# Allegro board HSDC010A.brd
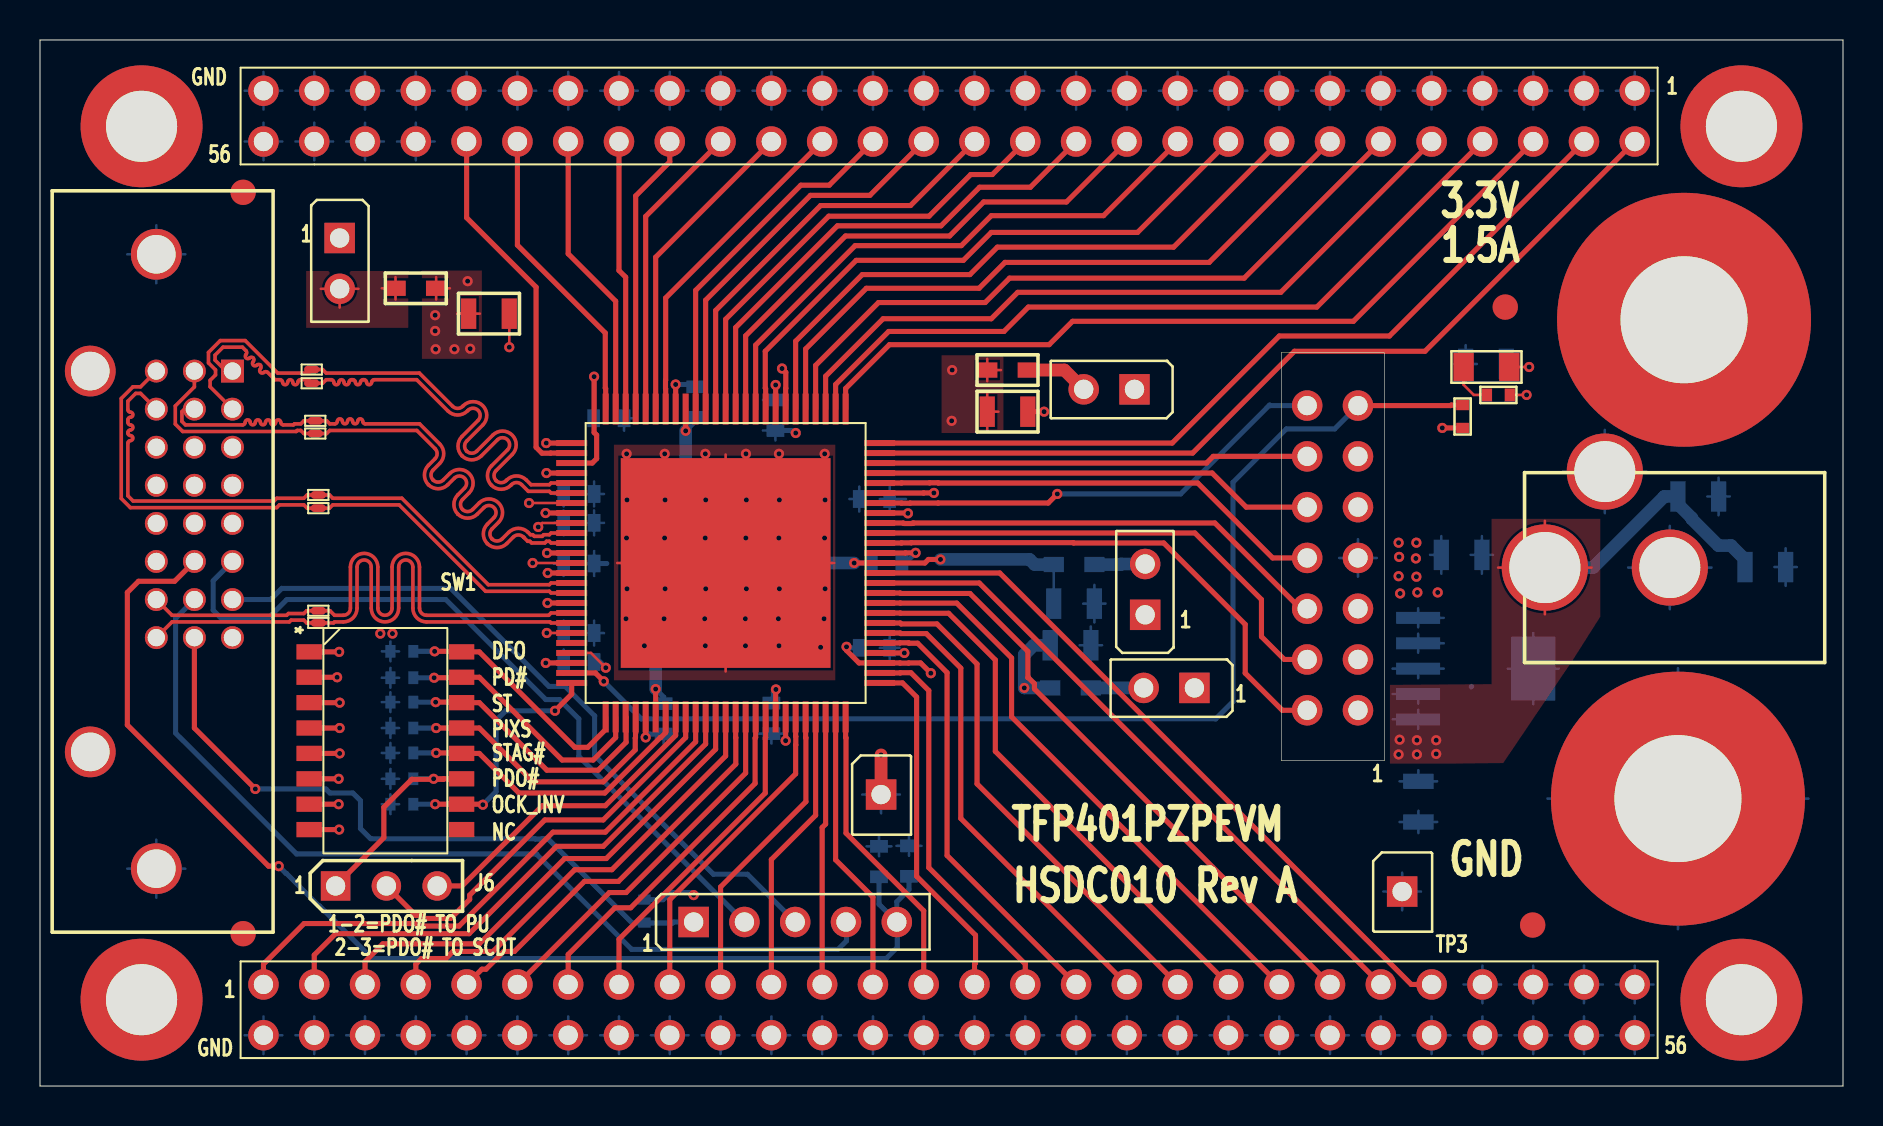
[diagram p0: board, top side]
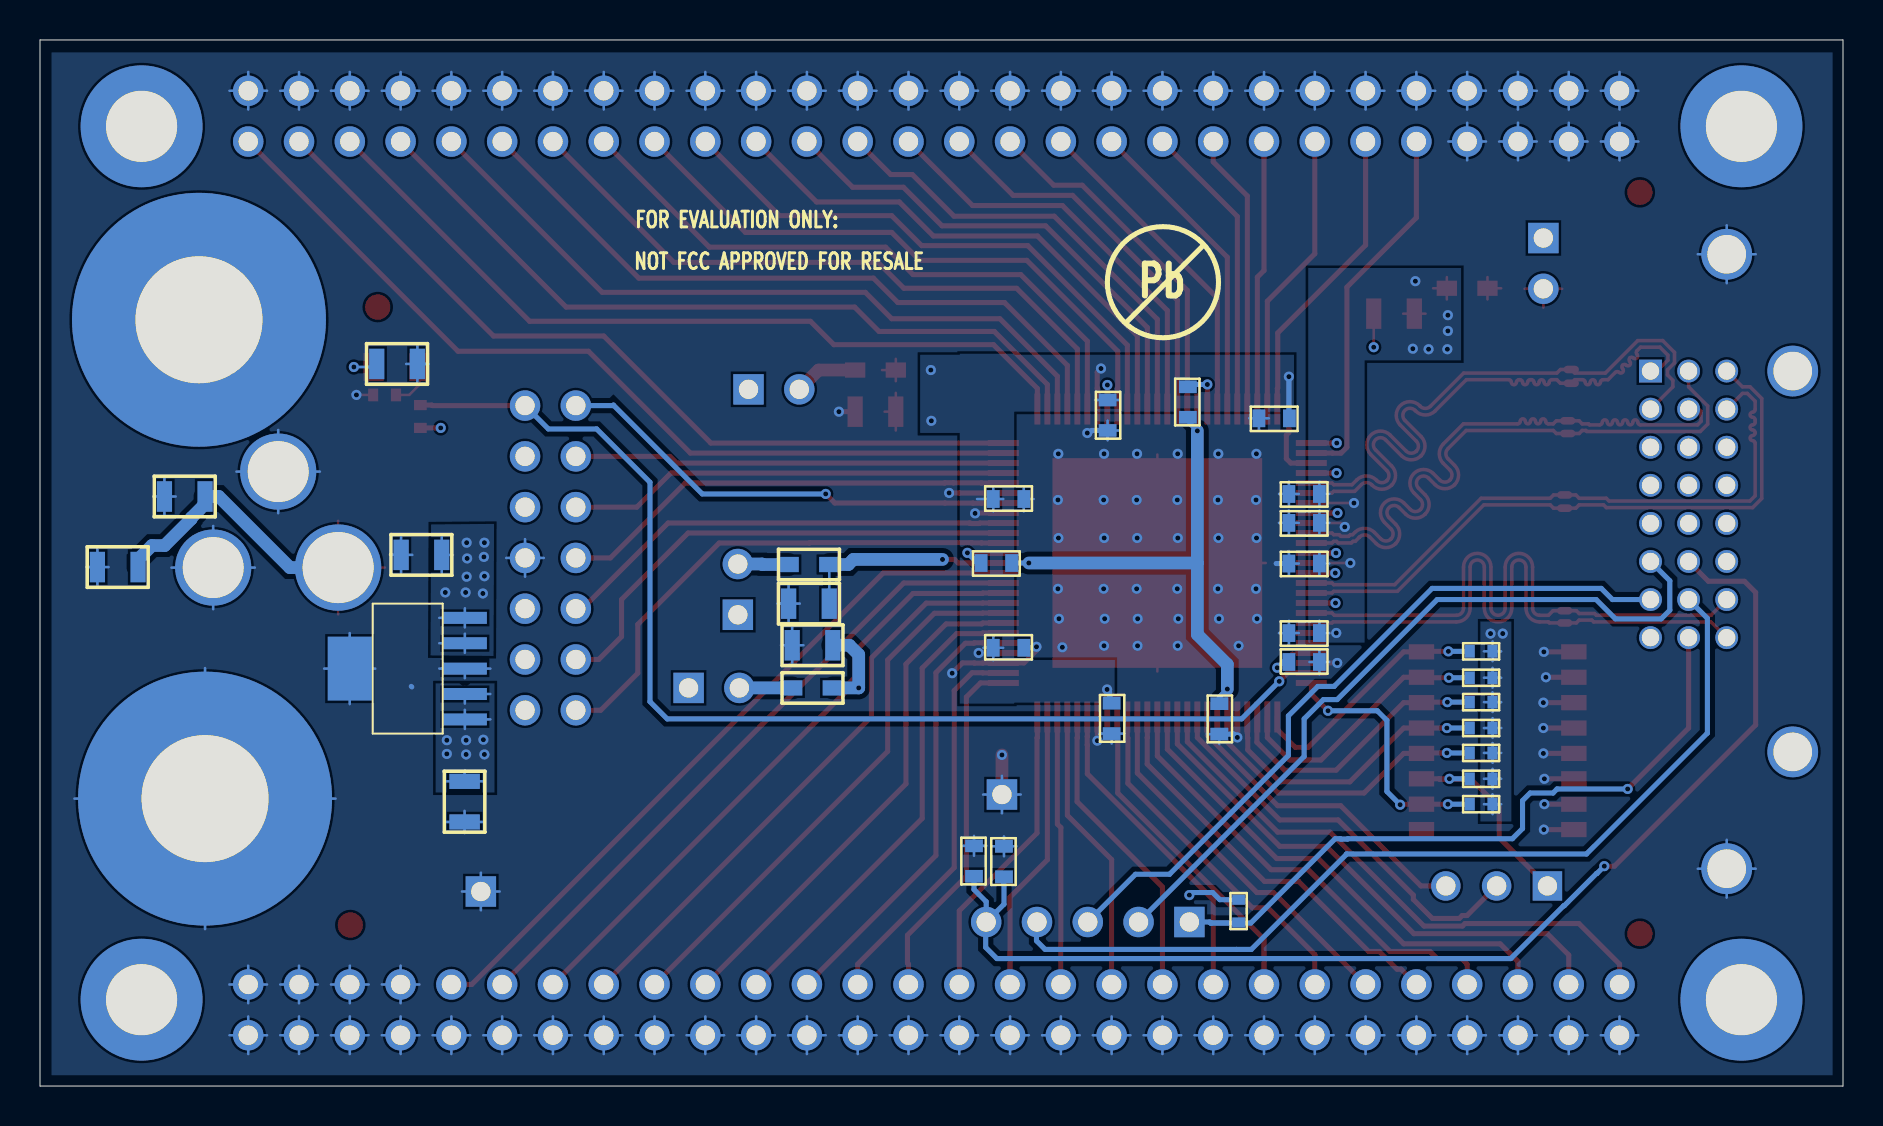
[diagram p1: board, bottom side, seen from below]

Outline 90.17 x 52.32 mm; copper layers: TOP, L2, L4, BOTTOM. Coordinates in mm from the lower left corner of the outline.
Outline path: 0,52.32 0,0 90.17,0 90.17,52.32 0,52.32

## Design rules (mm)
net group TMDS_CLK: nets RXCN_TP RXCP_TP
net group TMDS_RX0: nets RX0N_TP RX0P_TP
net group TMDS_RX1: nets RX1N_TP RX1P_TP
net group TMDS_RX2: nets RX2N_TP RX2P_TP

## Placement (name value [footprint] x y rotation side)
C1  0.1uF  [CC0603]  41.96 10.46 90 bottom
C2  0.01uF  [CC0603]  43.46 10.49 90 bottom
C3  10uF  [CC0805]  70.08 26.57 0 bottom
C4  0.1uF  [CC0603]  26.19 28.17 0 bottom
C5  0.1uF  [CC0603]  26.19 26.14 0 bottom
C6  0.1uF  [CC0603]  26.19 22.66 0 bottom
C7  0.1uF  [CC0603]  26.19 29.62 0 bottom
C8  22uF  [CC0805]  21.44 38.63 0 top
C9  22uF  [CC0805]  50.7 24.13 0 bottom
C10  0.1uF  [CC0603]  32.77 33.45 90 bottom
C11  0.1uF  [CC0603]  41.58 26.16 0 bottom
C12  0.1uF  [CC0603]  31.19 19.13 270 bottom
C13  22uF  [CC0805]  47.37 33.73 0 top
C14  0.1uF  [CC0603]  36.58 19.15 270 bottom
C15  0.1uF  [CC0603]  42.49 21.92 180 bottom
C16  0.1uF  [CC0603]  42.49 29.36 180 bottom
C17  0.1uF  [CC0603]  36.78 34.32 270 bottom
C18  0.1uF  [CC0603]  27.69 33.4 0 bottom
C19  22uF  [CC0805]  50.52 22.05 0 bottom
C20  0.1uF  [CC0603]  27.71 21.21 180 bottom
C21  10uF  [CC0805]  81.91 29.49 0 bottom
C22  10uF  [CC0805]  85.27 25.96 0 bottom
C23  10uF  [CC0805]  73.33 36.12 180 bottom
C24  10uF  [CC0805]  68.94 15.24 270 bottom
D1  LED Green 0805  [R0805]  71.2 35.97 0 top
J3  DVI Connector  [DVI_CONN_01]  9.63 35.76 270 top
J4  HEADER 1x5  [BERG1X5]  32.69 8.2 90 top
J5  HEADER 7X2  [BERG2X7]  65.91 18.8 180 top
J6  HEADER 3  [HDR_THVT_1X3_100]  14.78 10.01 90 top
J8  JUMPER  [BERG1X2]  14.99 42.42 0 top
J9  JUMPER  [BERG1X2]  55.27 23.57 180 top
J10  JUMPER  [BERG1X2]  54.74 34.85 270 top
J11  JUMPER  [BERG1X2]  57.73 19.91 270 top
J12  PHONE JACK-3  [PJ-202AH]  75.26 25.93 90 top
J13  HEADER 28x2  [HEADER2X28]  79.76 5.08 270 top
J14  HEADER 28x2  [HEADER2X28]  79.76 49.78 270 top
L1  BLM18RK601SN1D  [CAP0603]  17.78 39.9 0 top
L2  BLM18RK601SN1D  [CAP0603]  52.73 26.09 180 bottom
L3  BLM18RK601SN1D  [CAP0603]  49.4 35.81 180 top
L4  BLM18RK601SN1D  [CAP0603]  52.55 19.91 180 bottom
NOREF  -  [unnamed]  5.08 4.32 0 top
NOREF#2  -  [unnamed]  5.08 48.01 0 top
NOREF#3  -  [unnamed]  73.28 38.96 0 top
NOREF#4  -  [#2]  0 0 90 top
NOREF#5  -  [#2]  31.6 37.74 0 top
NOREF#6  -  [unnamed]  10.16 44.7 0 top
NOREF#7  -  [unnamed]  10.16 7.62 0 top
NOREF#8  -  [#2]  -45.95 -98.5 0 top
NOREF#9  -  [unnamed]  74.65 8.05 0 top
NOREF#10  -  [#2]  0 52.32 0 top
NOREF#11  -  [unnamed]  85.09 48.01 0 top
NOREF#12  -  [unnamed]  85.09 4.32 0 top
P1  Banana-Jack  [BANANA_JACK_250MIL]  82.22 38.33 0 top
P2  Banana-Jack  [BANANA_JACK_250MIL]  81.91 14.38 0 top
R1  33K  [R0402]  30.23 9.32 270 bottom
R2  33K  [R0402]  17.53 14.1 0 bottom
R3  33K  [R0402]  17.53 21.74 0 bottom
R4  33K  [R0402]  17.53 20.42 0 bottom
R5  33K  [R0402]  17.53 19.2 0 bottom
R6  33K  [R0402]  17.53 17.91 0 bottom
R7  33K  [R0402]  17.53 16.66 0 bottom
R8  33K  [R0402]  17.53 15.37 0 bottom
R9  10K  [R0402]  71.15 34.06 270 top
R10  330  [R0402]  72.36 34.57 0 top
SW1  SW DIP-8  [TDA08H0SK1]  17.27 17.27 270 top
TP1  TEST POINT  [TESTPOINTSMT_1]  13.59 35.84 270 top
TP2  TEST POINT  [TESTPOINTSMT_1]  13.92 29.57 90 top
TP3  TEST POINT  [BERG1X1]  68.12 9.73 0 top
TP4  TEST POINT  [TESTPOINTSMT_1]  13.59 35.15 270 top
TP5  TEST POINT  [TESTPOINTSMT_1]  13.92 28.91 90 top
TP6  TEST POINT  [BERG1X1]  42.06 14.58 0 top
TP7  TEST POINT  [TESTPOINTSMT_1]  13.77 33.27 270 top
TP8  TEST POINT  [TESTPOINTSMT_1]  13.92 23.77 270 top
TP9  TEST POINT  [TESTPOINTSMT_1]  13.77 32.64 270 top
TP10  TEST POINT  [TESTPOINTSMT_1]  13.92 23.16 270 top
U1  TFP401  [PZP-S-PQFP-G100]  34.29 26.16 90 top
U2  TPS7A4533  [DCQ_R-PDSO-G6]  71.78 20.88 0 bottom

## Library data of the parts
C1 C2 C4-C7 C10-C12 C14-C18 C20 = CAP
C3 C8 C9 C13 C19 = CAP POL
C21-C24 = CAP NP
D1 = DIODE
J3 = HEADER 28
J4 = HEADER 5
J5 = HEADER 7X2
J6 = HEADER 3
J8-J11 = JUMPER
J12 = PHONE JACK-3_0
J13 = HEADER 28x2_0
J14 = HEADER 28x2
L1-L4 = INDUCTOR
P1 P2 = Banana-Jack
R1-R10 = R
SW1 = SW DIP-8
TP1-TP10 = TEST POINT
U1 = TFP401
U2 = TPS7A4533

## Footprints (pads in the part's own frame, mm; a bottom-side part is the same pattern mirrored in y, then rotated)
BANANA_JACK_250MIL
  round 12.7 hole 6.35: 1(0,0)
BERG1X1
  rect 1.524x1.524 hole 0.965: 1(0,0)
BERG1X2
  rect 1.524x1.524 hole 0.965: 1(0,0)
  round 1.524 hole 0.965: 2(0,-2.54)
BERG1X5
  rect 1.524x1.524 hole 0.965: 1(0,0)
  round 1.524 hole 0.965: 2(0,-2.54) 3(0,-5.08) 4(0,-7.62) 5(0,-10.16)
BERG2X7
  round 1.524 hole 0.965: 1(0,0) 2(2.54,0) 3(0,-2.54) 4(2.54,-2.54) 5(0,-5.08) 6(2.54,-5.08) 7(0,-7.62) 8(2.54,-7.62) 9(0,-10.16) 10(2.54,-10.16) 11(0,-12.7) 12(2.54,-12.7) 13(0,-15.24) 14(2.54,-15.24)
CAP0603
  rect 1.016x0.762 smd: 1(0,0) 2(2.032,0)
CC0603
  rect 0.635x0.889 smd: 1(0,0) 2(1.524,0)
CC0805
  rect 0.762x1.524 smd: 1(0,0) 2(2.032,0)
DCQ_R-PDSO-G6
  rect 2.2x0.6 smd: 1(-2.858,2.54) 2(-2.858,1.27) 3(-2.858,0) 4(-2.858,-1.27) 5(-2.858,-2.54)
  rect 2.2x3.2 smd: 6(2.9,0)
DVI_CONN_01
  round 2.54 hole 1.93 unplated: (0,-7.112) (19.05,-7.112)
  rect 1.143x1.143 hole 0.864: 1(0,0)
  round 1.143 hole 0.864: 2(1.905,0) 3(3.81,0) 4(5.715,0) 5(7.62,0) 6(9.525,0) 7(11.43,0) 8(13.335,0) 9(0,-1.905) 10(1.905,-1.905) 11(3.81,-1.905) 12(5.715,-1.905) 13(7.62,-1.905) 14(9.525,-1.905) 15(11.43,-1.905) 16(13.335,-1.905) 17(0,-3.81) 18(1.905,-3.81) 19(3.81,-3.81) 20(5.715,-3.81) 21(7.62,-3.81) 22(9.525,-3.81) 23(11.43,-3.81) 24(13.335,-3.81)
  round 2.54 hole 1.93: 25(-5.842,-3.81) 26(24.892,-3.81)
HDR_THVT_1X3_100
  rect 1.473x1.473 hole 0.965: 1(0,0)
  round 1.473 hole 0.965: 2(0,-2.54) 3(0,-5.08)
HEADER2X28
  round 1.524 hole 0.965: 1(0,0) 2(2.54,0) 3(0,-2.54) 4(2.54,-2.54) 5(0,-5.08) 6(2.54,-5.08) 7(0,-7.62) 8(2.54,-7.62) 9(0,-10.16) 10(2.54,-10.16) 11(0,-12.7) 12(2.54,-12.7) 13(0,-15.24) 14(2.54,-15.24) 15(0,-17.78) 16(2.54,-17.78) 17(0,-20.32) 18(2.54,-20.32) 19(0,-22.86) 20(2.54,-22.86) 21(0,-25.4) 22(2.54,-25.4) 23(0,-27.94) 24(2.54,-27.94) 25(0,-30.48) 26(2.54,-30.48) 27(0,-33.02) 28(2.54,-33.02) 29(0,-35.56) 30(2.54,-35.56) 31(0,-38.1) 32(2.54,-38.1) 33(0,-40.64) 34(2.54,-40.64) 35(0,-43.18) 36(2.54,-43.18) 37(0,-45.72) 38(2.54,-45.72) 39(0,-48.26) 40(2.54,-48.26) 41(0,-50.8) 42(2.54,-50.8) 43(0,-53.34) 44(2.54,-53.34) 45(0,-55.88) 46(2.54,-55.88) 47(0,-58.42) 48(2.54,-58.42) 49(0,-60.96) 50(2.54,-60.96) 51(0,-63.5) 52(2.54,-63.5) 53(0,-66.04) 54(2.54,-66.04) 55(0,-68.58) 56(2.54,-68.58)
PJ-202AH
  round 4.318 hole 3.556: 1(0,0)
  round 3.81 hole 3.048: 2(4.801,-2.997) 3(0,-6.248)
PZP-S-PQFP-G100
  rect 1.55x0.3 smd: 1(-7.7,6) 2(-7.7,5.5) 3(-7.7,5) 4(-7.7,4.5) 5(-7.7,4) 6(-7.7,3.5) 7(-7.7,3) 8(-7.7,2.5) 9(-7.7,2) 10(-7.7,1.5) 11(-7.7,1) 12(-7.7,0.5) 13(-7.7,0) 14(-7.7,-0.5) 15(-7.7,-1) 16(-7.7,-1.5) 17(-7.7,-2) 18(-7.7,-2.5) 19(-7.7,-3) 20(-7.7,-3.5) 21(-7.7,-4) 22(-7.7,-4.5) 23(-7.7,-5) 24(-7.7,-5.5) 25(-7.7,-6) 51(7.7,-6) 52(7.7,-5.5) 53(7.7,-5) 54(7.7,-4.5) 55(7.7,-4) 56(7.7,-3.5) 57(7.7,-3) 58(7.7,-2.5) 59(7.7,-2) 60(7.7,-1.5) 61(7.7,-1) 62(7.7,-0.5) 63(7.7,0) 64(7.7,0.5) 65(7.7,1) 66(7.7,1.5) 67(7.7,2) 68(7.7,2.5) 69(7.7,3) 70(7.7,3.5) 71(7.7,4) 72(7.7,4.5) 73(7.7,5) 74(7.7,5.5) 75(7.7,6)
  rect 0.3x1.55 smd: 26(-6,-7.7) 27(-5.5,-7.7) 28(-5,-7.7) 29(-4.5,-7.7) 30(-4,-7.7) 31(-3.5,-7.7) 32(-3,-7.7) 33(-2.5,-7.7) 34(-2,-7.7) 35(-1.5,-7.7) 36(-1,-7.7) 37(-0.5,-7.7) 38(0,-7.7) 39(0.5,-7.7) 40(1,-7.7) 41(1.5,-7.7) 42(2,-7.7) 43(2.5,-7.7) 44(3,-7.7) 45(3.5,-7.7) 46(4,-7.7) 47(4.5,-7.7) 48(5,-7.7) 49(5.5,-7.7) 50(6,-7.7) 76(6,7.7) 77(5.5,7.7) 78(5,7.7) 79(4.5,7.7) 80(4,7.7) 81(3.5,7.7) 82(3,7.7) 83(2.5,7.7) 84(2,7.7) 85(1.5,7.7) 86(1,7.7) 87(0.5,7.7) 88(0,7.7) 89(-0.5,7.7) 90(-1,7.7) 91(-1.5,7.7) 92(-2,7.7) 93(-2.5,7.7) 94(-3,7.7) 95(-3.5,7.7) 96(-4,7.7) 97(-4.5,7.7) 98(-5,7.7) 99(-5.5,7.7) 100(-6,7.7)
  rect 10.49x10.49 smd: 101(0,0)
R0402
  rect 0.508x0.635 smd: 1(0,0) 2(1.143,0)
R0805
  rect 1.016x1.397 smd: 1(0,0) 2(2.286,0)
TDA08H0SK1
  rect 0.762x1.27 smd: 1(-4.445,-3.81) 2(-3.175,-3.81) 3(-1.905,-3.81) 4(-0.635,-3.81) 5(0.635,-3.81) 6(1.905,-3.81) 7(3.175,-3.81) 8(4.445,-3.81) 9(4.445,3.81) 10(3.175,3.81) 11(1.905,3.81) 12(0.635,3.81) 13(-0.635,3.81) 14(-1.905,3.81) 15(-3.175,3.81) 16(-4.445,3.81)
TESTPOINTSMT_1
  oval 0.381x0.762 smd: 1(0,0)
unnamed
  round 6.096 hole 3.556 unplated: (0,0)

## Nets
+3.3V: C3.1 C23.1 D1.2(A) J8.1 J9.1 J10.1 J11.1 P1.1(V) R1.1 R2.1 R3.1 R4.1 R5.1 R6.1 R7.1 R8.1 R9.2 U2.4(OUT) U2.5(SENSE)
+5V_DVI: C1.1 C2.1 J3.14 J4.5
AVDD: C4.1 C5.1 C6.1 C7.1 C8.1 L1.2 U1.82(AVDD1) U1.84(AVDD2) U1.88(AVDD3) U1.95(AVDD4)
DVDD: C9.1 C10.1 C11.1 C12.1 L2.2 U1.6(DVDD1) U1.38(DVDD2) U1.67(DVDD3)
GND_DVI: J3.15 J4.4
GND_POWER: C1.2 C2.2 C3.2 C4.2 C5.2 C6.2 C7.2 C8.2 C9.2 C10.2 C11.2 C12.2 C13.2 C14.2 C15.2 C16.2 C17.2 C18.2 C19.2 C20.2 C21.2 C22.2 C23.2 C24.2 J3.25 J3.26 J5.7 J12.2 J12.3 J13.1(55) J13.2(56) J13.3(53) J13.4(54) J13.5(51) J13.6(52) J13.7(49) J13.8(50) J13.10(48) J13.12(46) J13.14(44) J13.16(42) J13.18(40) J13.20(38) J13.22(36) J13.24(34) J13.26(32) J13.28(30) J13.30(28) J13.32(26) J13.34(24) J13.36(22) J13.38(20) J13.40(18) J13.42(16) J13.44(14) J13.46(12) J13.48(10) J13.50(8) J13.52(6) J13.54(4) J13.56(2) J14.1 J14.3 J14.5 J14.7 J14.9 J14.11 J14.13 J14.15 J14.17 J14.19 J14.21 J14.23 J14.25 J14.27 J14.29 J14.31 J14.33 J14.35 J14.37 J14.39 J14.41 J14.43 J14.45 J14.47 J14.49 J14.50 J14.51 J14.52 J14.53 J14.54 J14.55 J14.56 P2.1(V) R10.2 SW1.1(A1) SW1.2(A2) SW1.3(A3) SW1.4(A4) SW1.5(A5) SW1.6(A6) SW1.7(A7) SW1.8(A8) TP3.1 TP6.1 U1.5(DGND1) U1.19(OGND1) U1.28(OGND2) U1.39(DGND2) U1.45(OGND3) U1.58(OGND4) U1.68(DGND3) U1.76(OGND5) U1.79(AGND1) U1.83(AGND2) U1.87(AGND3) U1.89(AGND4) U1.92(AGND5) U1.98(PGND) U1.101(THERMAL PAD) U2.3(GND) U2.6(CHASIS)
BOARD_5V: C21.1 C22.1 C24.1 J12.1 U2.1(SHDN#) U2.2(IN)
DDC_CLK: J3.6 J4.2
DDC_DATA: J3.7 J4.3
HPD: J3.16 J4.1 R1.2
OVDD: C13.1 C14.1 C15.1 C16.1 C17.1 C18.1 L3.2 U1.18(OVDD1) U1.29(OVDD2) U1.43(OVDD3) U1.57(OVDD4) U1.78(OVDD5)
RX0N_TP: J3.17 TP5.1 U1.91(RX0N)
RX0P_TP: J3.18 TP2.1 U1.90(RX0P)
RX1N_TP: J3.9 TP9.1 U1.86(RX1N)
RX1P_TP: J3.10 TP7.1 U1.85(RX1P)
RX2N_TP: J3.1 TP4.1 U1.81(RX2N)
RX2P_TP: J3.2 TP1.1 U1.80(RX2P)
RXCN_TP: J3.24 TP10.1 U1.94(RXCN)
RXCP_TP: J3.23 TP8.1 U1.93(RXCP)
N03879: C19.1 C20.1 L4.2 U1.97(PVDD)
N04328: J9.2 L2.1
N04342: J10.2 L3.1
N04358: J11.2 L4.1
N05960: J13.55(1) U1.10(QE0)
N05964: J13.53(3) U1.11(QE1)
N05968: J13.51(5) U1.12(QE2)
N05972: J13.49(7) U1.13(QE3)
N05976: J13.47(9) U1.14(QE4)
N05980: J13.45(11) U1.15(QE5)
N05984: J13.43(13) U1.16(QE6)
N05988: J13.41(15) U1.17(QE7)
N05992: J13.39(17) U1.20(QE8)
N05996: J13.37(19) U1.21(QE9)
N06000: J13.35(21) U1.22(QE10)
N06004: J13.33(23) U1.23(QE11)
N06008: J13.31(25) U1.24(QE12)
N06012: J13.29(27) U1.25(QE13)
N06016: J13.27(29) U1.26(QE14)
N06020: J13.25(31) U1.27(QE15)
N06024: J13.23(33) U1.30(QE16)
N06028: J13.21(35) U1.31(QE17)
N06032: J13.19(37) U1.32(QE18)
N06036: J13.17(39) U1.33(QE19)
N06040: J13.15(41) U1.34(QE20)
N06044: J13.13(43) U1.35(QE21)
N06048: J13.11(45) U1.36(QE22)
N06052: J13.9(47) U1.37(QE23)
N06056: J14.48 U1.77(QO23)
N06060: J14.46 U1.75(QO22)
N06064: J14.44 U1.74(QO21)
N06068: J14.42 U1.73(QO20)
N06072: J14.40 U1.72(QO19)
N06076: J14.38 U1.71(QO18)
N06080: J14.36 U1.70(QO17)
N06084: J14.34 U1.69(QO16)
N06088: J14.32 U1.66(QO15)
N06092: J14.30 U1.65(QO14)
N06096: J14.28 U1.64(QO13)
N06100: J14.26 U1.63(QO12)
N06104: J14.24 U1.62(QO11)
N06108: J14.22 U1.61(QO10)
N06112: J14.20 U1.60(QO9)
N06116: J14.18 U1.59(QO8)
N06120: J14.16 U1.56(QO7)
N06124: J14.14 U1.55(QO6)
N06128: J14.12 U1.54(QO5)
N06132: J14.10 U1.53(QO4)
N06136: J14.8 U1.52(QO3)
N06140: J14.6 U1.51(QO2)
N06144: J14.4 U1.50(QO1)
N06148: J14.2 U1.49(QO0)
N13798: R3.2 SW1.16(B1) U1.1(DFO)
N13802: R4.2 SW1.15(B2) U1.2(PD#)
N13806: R5.2 SW1.14(B3) U1.3(ST)
N13810: R6.2 SW1.13(B4) U1.4(PIXS)
N13814: R7.2 SW1.12(B5) U1.7(STAG#)
N13818: J6.1 R8.2 SW1.11(B6)
N13822: R2.2 SW1.10(B7) U1.100(OCK_INV)
N14714: J6.2 U1.9(PDO#)
N14769: J6.3 U1.8(SCDT)
N17734: J5.14 U1.44(ODCK)
N17746: J5.12 U1.48(HSYNC)
N17750: J5.10 U1.47(VSYNC)
N17754: J5.8 U1.46(DE)
N17758: J5.6 U1.42(CTL3)
N17762: J5.4 U1.41(CTL2)
N17766: J5.2 U1.40(CTL1)
N17770: J5.13 R9.1 U1.99(RSVD)
N35472: D1.1(K) R10.1
N40612: J8.2 L1.1

Pads without a net: J3 3 4 5 8 11 12 13 19 20 21 22; J5 1 3 5 9 11; SW1 9; U1 96

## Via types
v1: diameter 0.508, hole 0.254, TOP to BOTTOM, 119 vias

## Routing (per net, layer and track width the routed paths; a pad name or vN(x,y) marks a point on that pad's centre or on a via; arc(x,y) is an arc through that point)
+3.3V: length 65.9
  TOP w0.127: D1.2 v1(74.47,35.97)
  TOP w0.254: R9.2 v1(70.13,32.92)
  L4 w0.381: J10.1 54.74,35.73 ; J10.1 53.86,34.85 ; J10.1 54.74,33.97 ; J10.1 55.61,34.85 ; 54.39,23.57 J9.1 ; J9.1 55.27,24.45 ; J9.1 55.27,22.69 ; J9.1 56.15,23.57 ; J8.1 14.99,43.29 ; J8.1 14.11,42.42 ; J8.1 15.86,42.42 ; J8.1 14.99,41.54 ; 57.73,19.04 J11.1 ; J11.1 57.73,20.79 ; J11.1 58.61,19.91 ; J11.1 56.86,19.91 ; P1.1 82.22,44.86 ; P1.1 82.22,31.8 ; P1.1 75.69,38.33 ; P1.1 88.75,38.33
  BOTTOM w0.127: 17.53,14.87 R8.1 ; R8.1 17.53,15.86 ; R8.1 17.09,15.37 ; R8.1 17.96,15.37 ; 17.09,21.74 R3.1 ; R3.1 17.53,21.25 ; R3.1 17.96,21.74 ; R3.1 17.53,22.24 ; R6.1 17.96,17.91 ; R6.1 17.53,18.4 ; R6.1 17.53,17.41 ; R6.1 17.09,17.91 ; 17.53,18.71 R5.1 ; R5.1 17.96,19.2 ; R5.1 17.09,19.2 ; R5.1 17.53,19.7 ; 17.09,20.42 R4.1 ; R4.1 17.96,20.42 ; R4.1 17.53,20.92 ; R4.1 17.53,19.93 ; 17.09,16.66 R7.1 ; R7.1 17.96,16.66 ; R7.1 17.53,17.16 ; R7.1 17.53,16.17 ; U2.5 68.92,23.9 ; U2.5 68.92,22.94 ; U2.5 70.2,23.42 ; R2.1 17.96,14.1 ; R2.1 17.53,14.59 ; R2.1 17.09,14.1 ; R2.1 17.53,13.6 ; C3.1 70.08,27.51 ; C3.1 70.08,25.63 ; C3.1 69.52,26.57 ; U2.4 68.92,22.63 ; U2.4 68.92,21.67 ; U2.4 70.2,22.15 ; C23.1 D1.2 v1(74.47,35.97)
  BOTTOM w0.254: v1(32.69,9.55) 32.56,9.68 31.52,9.68 31.17,9.32 R1.1
  vias: v1(17.02,22.63) v1(17.63,22.63) v1(67.94,27.18) v1(67.97,26.47) v1(67.94,25.5) v1(68.02,24.64) v1(68.83,27.18) v1(68.81,26.39) v1(68.83,25.48) v1(68.88,24.69) v1(69.9,24.69)
+5V_DVI: length 60.6
  TOP w0.254: J3.14 6.73,25.25 4.93,25.25 4.37,24.69 4.37,18.06 11.43,11 v1(11.94,11)
  BOTTOM w0.254: J4.5 41.96,9.09 C1.1 ; J4.5 42.85,9.22 43.46,9.83 C2.1 ; J4.5 42.88,8.18 42.88,6.93 42.32,6.38 16.61,6.38 13.97,9.02 13.94,9.02 12.32,10.64 12.3,10.64 v1(11.94,11)
AVDD: length 16.3
  TOP w0.127: 22,38.63 C8.1 20.88,38.63 ; U1.88 v1(24.64,26.16) ; L1.2 20.5,39.9 ; L1.2 19.81,40.46 ; L1.2 19.81,39.34 ; U1.84 25.11,28.16 v1(24.92,27.97) ; U1.82 v1(24.46,29.16) ; U1.95 v1(25.34,22.66)
  BOTTOM w0.127: C5.1 26.19,26.76 ; C5.1 25.69,26.14 ; C5.1 26.19,25.51 ; 25.69,28.17 C4.1 ; C4.1 26.19,27.55 ; C4.1 26.19,28.79 ; 25.69,22.66 C6.1 26.19,23.28 ; 25.69,29.62 C7.1 ; C7.1 26.19,28.99 ; C7.1 26.19,30.24
  vias: v1(19.76,38.56) v1(19.76,37.77) v1(19.79,36.86) v1(20.73,36.86) v1(21.39,40.26) v1(21.51,36.88)
DVDD: length 39.2
  TOP w0.254: U1.67 v1(32.29,32.77) ; v1(45.03,26.34) 44.43,26.34 44.25,26.16 U1.38 v1(40.72,26.16) ; U1.6 v1(30.79,19.86)
  BOTTOM w0.127: C9.1 L2.2
  BOTTOM w0.254: v1(30.79,19.86) 31.19,19.46 C12.1 ; C11.1 v1(40.72,26.16) ; C10.1 32.77,33.4 32.65,33.29 32.65,33.13 v1(32.29,32.77)
  BOTTOM w0.635: L2.2 49.75,26.09 49.49,26.34 v1(45.03,26.34) ; 32.29,26.16 32.29,22.59 30.79,21.09 v1(30.79,19.86) ; 32.29,26.16 v1(32.29,32.77) ; 32.29,26.16 v1(40.72,26.16)
GND_DVI: length 46.2
  BOTTOM w0.254: J3.15 6.78,23.39 6.78,17.65 12.83,11.61 24.83,11.61 24.85,11.58 29.59,6.83 30.33,6.83 39.9,6.83 40.34,7.26 40.34,8.18 J4.4
GND_POWER: length 715.4
  TOP w0.127: 34.29,20.74 U1.101 ; U1.101 34.29,31.58 ; U1.101 39.71,26.16 ; U1.101 28.87,26.16 ; C8.2 v1(23.47,36.96) ; R10.2 v1(74.35,34.57)
  TOP w0.254: 13.46,14.1 v1(14.94,14.1) ; U1.5 v1(30.29,17.44) ; v1(44.55,20.65) 44.04,21.16 43.45,21.16 43.44,21.15 43.02,21.15 43.01,21.16 U1.28 40.96,21.16 40.34,21.79 v1(40.34,21.97) ; SW1.5 v1(14.99,16.64) ; SW1.1 v1(14.96,21.72) ; SW1.4 v1(14.99,17.91) ; U1.89 v1(25.39,25.66) ; SW1.3 v1(14.99,19.18) ; U1.76 v1(25.32,32.16) ; C13.2 v1(50.22,33.73) ; v1(43.79,26.67) 43.28,26.67 43.27,26.66 U1.39 ; U1.87 v1(25.36,26.66) ; U1.83 v1(25.28,28.66) ; SW1.8 v1(14.96,12.83) ; v1(44.7,29.67) 44.2,29.67 44.19,29.66 U1.45 ; U1.19 v1(37.29,17.27) ; U1.92 v1(25.38,24.16) ; SW1.6 v1(14.94,15.37) ; U1.58 v1(36.79,35.07) ; SW1.2 v1(14.86,20.45) ; U1.79 v1(25.33,30.66) ; U1.68 v1(31.79,35.09) ; U1.98 v1(25.29,21.16)
  TOP w0.635: TP6.1 v1(42.06,16.56)
  L2 w0.381: 28.08,2.54 J13.42 ; J13.42 29.83,2.54 ; J13.42 28.96,3.42 ; J13.42 28.96,1.66 ; 38.24,2.54 J13.34 ; J13.34 39.12,3.42 ; J13.34 39.99,2.54 ; J13.34 39.12,1.66 ; TP6.1 42.94,14.58 ; TP6.1 42.06,13.7 ; TP6.1 42.06,15.46 ; TP6.1 41.19,14.58 ; 43.32,49.78 J14.29 ; J14.29 45.07,49.78 ; J14.29 44.2,48.91 ; J14.29 44.2,50.66 ; 10.3,47.24 J14.56 ; J14.56 11.18,46.37 ; J14.56 11.18,48.12 ; J14.56 12.05,47.24 ; 71.26,5.08 J13.7 ; J13.7 73.01,5.08 ; J13.7 72.14,5.96 ; J13.7 72.14,4.2 ; 15.38,2.54 J13.52 ; J13.52 17.13,2.54 ; J13.52 16.26,1.66 ; J13.52 16.26,3.42 ; 46.74,1.66 J13.28 ; J13.28 46.74,3.42 ; J13.28 45.86,2.54 ; J13.28 47.61,2.54 ; J13.20 56.9,3.42 ; J13.20 56.9,1.66 ; J13.20 56.02,2.54 ; J13.20 57.77,2.54 ; 61.98,48.91 J14.15 ; J14.15 61.1,49.78 ; J14.15 61.98,50.66 ; J14.15 62.85,49.78 ; J14.25 49.28,50.66 ; J14.25 50.15,49.78 ; J14.25 49.28,48.91 ; J14.25 48.4,49.78 ; 17.92,49.78 J14.49 ; J14.49 19.67,49.78 ; J14.49 18.8,48.91 ; J14.49 18.8,50.66 ; J13.44 26.42,3.42 ; J13.44 25.54,2.54 ; J13.44 26.42,1.66 ; J13.44 27.29,2.54 ; 4.37,10.87 J3.26 ; J3.26 5.82,9.42 ; J3.26 5.82,12.32 ; J3.26 7.26,10.87 ; J14.31 42.53,49.78 ; J14.31 41.66,48.91 ; J14.31 40.78,49.78 ; J14.31 41.66,50.66 ; 63.64,49.78 J14.13 ; J14.13 64.52,48.91 ; J14.13 65.39,49.78 ; J14.13 64.52,50.66 ; J13.8 72.14,3.42 ; J13.8 73.01,2.54 ; J13.8 72.14,1.66 ; J13.8 71.26,2.54 ; J14.45 23.88,50.66 ; J14.45 24.75,49.78 ; J14.45 23,49.78 ; J14.45 23.88,48.91 ; 75.39,14.38 P2.1 ; P2.1 88.44,14.38 ; P2.1 81.91,7.85 ; P2.1 81.91,20.9 ; J14.39 31.5,50.66 ; J14.39 30.62,49.78 ; J14.39 31.5,48.91 ; J14.39 32.37,49.78 ; 71.26,49.78 J14.7 ; J14.7 73.01,49.78 ; J14.7 72.14,48.91 ; J14.7 72.14,50.66 ; J13.18 60.31,2.54 ; J13.18 59.44,1.66 ; J13.18 58.56,2.54 ; J13.18 59.44,3.42 ; J13.48 22.21,2.54 ; J13.48 20.46,2.54 ; J13.48 21.34,3.42 ; J13.48 21.34,1.66 ; J13.30 44.2,3.42 ; J13.30 43.32,2.54 ; J13.30 45.07,2.54 ; J13.30 44.2,1.66 ; J13.4 77.22,3.42 ; J13.4 78.09,2.54 ; J13.4 77.22,1.66 ; J13.4 76.34,2.54 ; J14.33 39.99,49.78 ; J14.33 39.12,48.91 ; J14.33 39.12,50.66 ; J14.33 38.24,49.78 ; 12.84,49.78 J14.53 ; J14.53 14.59,49.78 ; J14.53 13.72,48.91 ; J14.53 13.72,50.66 ; 74.68,1.66 J13.6 ; J13.6 73.8,2.54 ; J13.6 75.55,2.54 ; J13.6 74.68,3.42 ; J13.46 24.75,2.54 ; J13.46 23,2.54 ; J13.46 23.88,1.66 ; J13.46 23.88,3.42 ; J13.38 34.91,2.54 ; J13.38 33.16,2.54 ; J13.38 34.04,3.42 ; J13.38 34.04,1.66 ; 56.02,49.78 J14.19 ; J14.19 57.77,49.78 ; J14.19 56.9,48.91 ; J14.19 56.9,50.66 ; J14.54 13.72,48.12 ; J14.54 12.84,47.24 ; J14.54 14.59,47.24 ; J14.54 13.72,46.37 ; J14.50 19.67,47.24 ; J14.50 18.8,46.37 ; J14.50 17.92,47.24 ; J14.50 18.8,48.12 ; 13.72,1.66 J13.54 ; J13.54 13.72,3.42 ; J13.54 14.59,2.54 ; J13.54 12.84,2.54 ; J14.1 79.76,50.66 ; J14.1 79.76,48.91 ; J14.1 78.88,49.78 ; J14.1 80.63,49.78 ; 74.68,4.2 J13.5 ; J13.5 73.8,5.08 ; J13.5 75.55,5.08 ; J13.5 74.68,5.96 ; J13.26 49.28,3.42 ; J13.26 49.28,1.66 ; J13.26 50.15,2.54 ; J13.26 48.4,2.54 ; 61.98,1.66 J13.16 ; J13.16 62.85,2.54 ; J13.16 61.1,2.54 ; J13.16 61.98,3.42 ; 51.82,48.91 J14.23 ; J14.23 51.82,50.66 ; J14.23 50.94,49.78 ; J14.23 52.69,49.78 ; J13.10 70.47,2.54 ; J13.10 69.6,3.42 ; J13.10 68.72,2.54 ; J13.10 69.6,1.66 ; 33.16,49.78 J14.37 ; J14.37 34.04,48.91 ; J14.37 34.91,49.78 ; J14.37 34.04,50.66 ; 78.88,5.08 J13.1 ; J13.1 79.76,4.2 ; J13.1 80.63,5.08 ; J13.1 79.76,5.96 ; J12.2 80.34,30.73 ; J12.2 76.17,30.73 ; J12.2 78.26,32.82 ; J12.2 78.26,28.65 ; J12.3 81.51,28.02 ; J12.3 83.59,25.93 ; J12.3 81.51,23.85 ; J12.3 79.43,25.93 ; 4.37,41.61 J3.25 ; J3.25 5.82,40.16 ; J3.25 7.26,41.61 ; J3.25 5.82,43.05 ; 18.8,1.66 J13.50 ; J13.50 19.67,2.54 ; J13.50 17.92,2.54 ; J13.50 18.8,3.42 ; J14.11 67.93,49.78 ; J14.11 67.06,48.91 ; J14.11 66.18,49.78 ; J14.11 67.06,50.66 ; J14.52 17.13,47.24 ; J14.52 16.26,48.12 ; J14.52 15.38,47.24 ; J14.52 16.26,46.37 ; J14.47 21.34,50.66 ; J14.47 21.34,48.91 ; J14.47 20.46,49.78 ; J14.47 22.21,49.78 ; J14.3 78.09,49.78 ; J14.3 77.22,48.91 ; J14.3 77.22,50.66 ; J14.3 76.34,49.78 ; J13.56 11.18,3.42 ; J13.56 10.3,2.54 ; J13.56 11.18,1.66 ; J13.56 12.05,2.54 ; 30.62,2.54 J13.40 ; J13.40 31.5,3.42 ; J13.40 32.37,2.54 ; J13.40 31.5,1.66 ; J13.24 52.69,2.54 ; J13.24 50.94,2.54 ; J13.24 51.82,3.42 ; J13.24 51.82,1.66 ; J14.17 59.44,50.66 ; J14.17 59.44,48.91 ; J14.17 60.31,49.78 ; J14.17 58.56,49.78 ; J14.27 46.74,50.66 ; J14.27 47.61,49.78 ; J14.27 45.86,49.78 ; J14.27 46.74,48.91 ; J14.9 69.6,50.66 ; J14.9 68.72,49.78 ; J14.9 70.47,49.78 ; J14.9 69.6,48.91 ; 54.36,1.66 J13.22 ; J13.22 53.48,2.54 ; J13.22 54.36,3.42 ; J13.22 55.23,2.54 ; 77.22,4.2 J13.3 ; J13.3 77.22,5.96 ; J13.3 76.34,5.08 ; J13.3 78.09,5.08 ; J14.55 11.18,50.66 ; J14.55 12.05,49.78 ; J14.55 11.18,48.91 ; J14.55 10.3,49.78 ; J13.32 41.66,3.42 ; J13.32 40.78,2.54 ; J13.32 41.66,1.66 ; J13.32 42.53,2.54 ; 74.68,48.91 J14.5 ; J14.5 73.8,49.78 ; J14.5 74.68,50.66 ; J14.5 75.55,49.78 ; J14.35 36.58,50.66 ; J14.35 37.45,49.78 ; J14.35 36.58,48.91 ; J14.35 35.7,49.78 ; 28.96,48.91 J14.41 ; J14.41 28.08,49.78 ; J14.41 29.83,49.78 ; J14.41 28.96,50.66 ; J13.12 67.93,2.54 ; J13.12 67.06,1.66 ; J13.12 66.18,2.54 ; J13.12 67.06,3.42 ; J13.2 80.63,2.54 ; J13.2 79.76,1.66 ; J13.2 79.76,3.42 ; J13.2 78.88,2.54 ; J14.51 17.13,49.78 ; J14.51 16.26,48.91 ; J14.51 16.26,50.66 ; J14.51 15.38,49.78 ; J14.21 54.36,50.66 ; J14.21 53.48,49.78 ; J14.21 55.23,49.78 ; J14.21 54.36,48.91 ; TP3.1 68.12,10.6 ; TP3.1 68.12,8.85 ; TP3.1 69,9.73 ; TP3.1 67.25,9.73 ; 25.54,49.78 J14.43 ; J14.43 26.42,50.66 ; J14.43 27.29,49.78 ; J14.43 26.42,48.91 ; J5.7 65.91,27.29 ; J5.7 66.79,26.42 ; J5.7 65.04,26.42 ; J5.7 65.91,25.54 ; 36.58,1.66 J13.36 ; J13.36 37.45,2.54 ; J13.36 35.7,2.54 ; J13.36 36.58,3.42 ; 63.64,2.54 J13.14 ; J13.14 64.52,3.42 ; J13.14 64.52,1.66 ; J13.14 65.39,2.54
  BOTTOM w0.127: 67.18,9.73 TP3.1 ; TP3.1 69.06,9.73 ; TP3.1 68.12,8.79 ; TP3.1 68.12,10.67 ; J14.49 19.74,49.78 ; J14.49 17.86,49.78 ; J14.49 18.8,50.72 ; J14.49 18.8,48.84 ; J13.24 51.82,3.48 ; J13.24 52.76,2.54 ; J13.24 51.82,1.6 ; J13.24 50.88,2.54 ; 40.72,49.78 J14.31 ; J14.31 41.66,48.84 ; J14.31 41.66,50.72 ; J14.31 42.6,49.78 ; 72.14,4.14 J13.7 ; J13.7 71.2,5.08 ; J13.7 72.14,6.02 ; J13.7 73.08,5.08 ; C24.2 69.88,13.21 ; C24.2 68,13.21 ; C24.2 68.94,13.77 ; C24.2 68.94,12.65 ; 63.58,2.54 J13.14 ; J13.14 64.52,1.6 ; J13.14 65.46,2.54 ; J13.14 64.52,3.48 ; C17.2 36.78,33.29 ; C17.2 36.16,32.79 ; C17.2 36.78,32.3 ; 33.1,2.54 J13.38 ; J13.38 34.04,1.6 ; J13.38 34.04,3.48 ; J13.38 34.98,2.54 ; 49.28,48.84 J14.25 ; J14.25 49.28,50.72 ; J14.25 50.22,49.78 ; J14.25 48.34,49.78 ; J14.37 34.98,49.78 ; J14.37 33.1,49.78 ; J14.37 34.04,48.84 ; J14.37 34.04,50.72 ; 45.8,2.54 J13.28 ; J13.28 46.74,3.48 ; J13.28 47.68,2.54 ; J13.28 46.74,1.6 ; C20.2 26.19,21.83 ; C20.2 26.19,20.59 ; C20.2 26.68,21.21 ; C20.2 25.69,21.21 ; 18.8,46.3 J14.50 ; J14.50 19.74,47.24 ; J14.50 18.8,48.18 ; J14.50 17.86,47.24 ; J13.36 37.52,2.54 ; J13.36 35.64,2.54 ; J13.36 36.58,3.48 ; J13.36 36.58,1.6 ; J13.26 50.22,2.54 ; J13.26 48.34,2.54 ; J13.26 49.28,3.48 ; J13.26 49.28,1.6 ; 10.24,47.24 J14.56 ; J14.56 11.18,48.18 ; J14.56 12.12,47.24 ; J14.56 11.18,46.3 ; 41.12,14.58 TP6.1 ; TP6.1 42.06,15.52 ; TP6.1 42.06,13.64 ; TP6.1 43,14.58 ; 41.96,11.49 C1.2 ; C1.2 42.58,11.99 ; C1.2 41.34,11.99 ; C1.2 41.96,12.48 ; 27.22,29.62 C7.2 ; C7.2 27.71,28.99 ; C7.2 28.21,29.62 ; C7.2 27.71,30.24 ; J14.9 69.6,50.72 ; J14.9 70.54,49.78 ; J14.9 68.66,49.78 ; J14.9 69.6,48.84 ; J3.25 7.26,41.61 ; J3.25 5.82,40.16 ; J3.25 5.82,43.05 ; J3.25 4.37,41.61 ; C23.2 71.3,37.06 ; C23.2 71.86,36.12 ; C23.2 71.3,35.18 ; C23.2 70.74,36.12 ; 13.72,1.6 J13.54 ; J13.54 13.72,3.48 ; J13.54 14.66,2.54 ; J13.54 12.78,2.54 ; 36.58,48.84 J14.35 ; J14.35 37.52,49.78 ; J14.35 35.64,49.78 ; J14.35 36.58,50.72 ; J13.5 75.62,5.08 ; J13.5 73.74,5.08 ; J13.5 74.68,6.02 ; J13.5 74.68,4.14 ; 76.17,30.73 J12.2 ; J12.2 78.26,32.82 ; J12.2 78.26,28.65 ; J12.2 80.34,30.73 ; 72.14,48.84 J14.7 ; J14.7 72.14,50.72 ; J14.7 71.2,49.78 ; J14.7 73.08,49.78 ; J13.44 26.42,3.48 ; J13.44 26.42,1.6 ; J13.44 25.48,2.54 ; J13.44 27.36,2.54 ; J14.1 79.76,50.72 ; J14.1 78.82,49.78 ; J14.1 79.76,48.84 ; J14.1 80.7,49.78 ; C19.2 53.11,22.05 ; C19.2 52.55,21.11 ; C19.2 51.99,22.05 ; C19.2 52.55,22.99 ; J14.54 14.66,47.24 ; J14.54 12.78,47.24 ; J14.54 13.72,46.3 ; J14.54 13.72,48.18 ; 86.74,25.96 C22.2 ; C22.2 87.86,25.96 ; C22.2 87.3,25.02 ; C22.2 87.3,26.9 ; 31.19,17.11 C12.2 31.81,17.6 ; 75.39,14.38 P2.1 ; P2.1 81.91,7.85 ; P2.1 88.44,14.38 ; P2.1 81.91,20.9 ; 55.96,49.78 J14.19 ; J14.19 56.9,50.72 ; J14.19 57.84,49.78 ; J14.19 56.9,48.84 ; J14.27 46.74,50.72 ; J14.27 46.74,48.84 ; J14.27 45.8,49.78 ; J14.27 47.68,49.78 ; J14.47 21.34,50.72 ; J14.47 21.34,48.84 ; J14.47 22.28,49.78 ; J14.47 20.4,49.78 ; J14.17 60.38,49.78 ; J14.17 59.44,50.72 ; J14.17 59.44,48.84 ; J14.17 58.5,49.78 ; J13.56 11.18,3.48 ; J13.56 10.24,2.54 ; J13.56 12.12,2.54 ; J13.56 11.18,1.6 ; 40.72,2.54 J13.32 ; J13.32 41.66,1.6 ; J13.32 42.6,2.54 ; J13.32 41.66,3.48 ; 74.68,48.84 J14.5 ; J14.5 74.68,50.72 ; J14.5 73.74,49.78 ; J14.5 75.62,49.78 ; 27.22,22.66 C6.2 ; C6.2 27.71,23.28 ; C6.2 27.71,22.03 ; C6.2 28.21,22.66 ; 10.24,49.78 J14.55 ; J14.55 12.12,49.78 ; J14.55 11.18,48.84 ; J14.55 11.18,50.72 ; C18.2 29.71,33.4 ; C18.2 28.71,33.4 ; C18.2 29.21,32.78 ; 23.88,48.84 J14.45 ; J14.45 22.94,49.78 ; J14.45 23.88,50.72 ; J14.45 24.82,49.78 ; U2.3 70.2,20.88 ; U2.3 67.64,20.88 ; U2.3 68.92,20.4 ; 71.55,26.57 C3.2 ; C3.2 72.11,25.63 ; C3.2 72.67,26.57 ; C3.2 72.11,27.51 ; J13.10 69.6,3.48 ; J13.10 70.54,2.54 ; J13.10 69.6,1.6 ; J13.10 68.66,2.54 ; J14.23 52.76,49.78 ; J14.23 50.88,49.78 ; J14.23 51.82,48.84 ; J14.23 51.82,50.72 ; J13.20 56.9,3.48 ; J13.20 56.9,1.6 ; J13.20 57.84,2.54 ; J13.20 55.96,2.54 ; C16.2 40.97,29.98 ; C16.2 40.97,28.74 ; C16.2 40.47,29.36 ; 61.98,48.84 J14.15 ; J14.15 61.98,50.72 ; J14.15 61.04,49.78 ; J14.15 62.92,49.78 ; J3.26 5.82,12.32 ; J3.26 7.26,10.87 ; J3.26 5.82,9.42 ; J3.26 4.37,10.87 ; 74.68,19.1 U2.6 ; U2.6 73.4,20.88 ; U2.6 74.68,22.66 ; U2.6 75.96,20.88 ; 72.14,1.6 J13.8 ; J13.8 71.2,2.54 ; J13.8 73.08,2.54 ; J13.8 72.14,3.48 ; 15.32,2.54 J13.52 ; J13.52 17.2,2.54 ; J13.52 16.26,1.6 ; J13.52 16.26,3.48 ; J14.41 29.9,49.78 ; J14.41 28.02,49.78 ; J14.41 28.96,50.72 ; J14.41 28.96,48.84 ; 65.91,25.48 J5.7 ; J5.7 64.97,26.42 ; J5.7 65.91,27.36 ; J5.7 66.85,26.42 ; 27.22,28.17 C4.2 ; C4.2 27.71,28.79 ; C4.2 27.71,27.55 ; C4.2 28.21,28.17 ; J13.42 29.9,2.54 ; J13.42 28.02,2.54 ; J13.42 28.96,1.6 ; J13.42 28.96,3.48 ; J14.43 27.36,49.78 ; J14.43 26.42,50.72 ; J14.43 25.48,49.78 ; J14.43 26.42,48.84 ; 67.06,1.6 J13.12 ; J13.12 66.12,2.54 ; J13.12 67.06,3.48 ; J13.12 68,2.54 ; J13.30 44.2,3.48 ; J13.30 43.26,2.54 ; J13.30 45.14,2.54 ; J13.30 44.2,1.6 ; 15.32,47.24 J14.52 ; J14.52 16.26,48.18 ; J14.52 16.26,46.3 ; J14.52 17.2,47.24 ; 22.94,2.54 J13.46 ; J13.46 23.88,1.6 ; J13.46 23.88,3.48 ; J13.46 24.82,2.54 ; 81.51,23.85 J12.3 ; J12.3 81.51,28.02 ; J12.3 79.43,25.93 ; J12.3 83.59,25.93 ; 77.22,1.6 J13.4 ; J13.4 77.22,3.48 ; J13.4 78.16,2.54 ; J13.4 76.28,2.54 ; J13.1 79.76,6.02 ; J13.1 79.76,4.14 ; J13.1 78.82,5.08 ; J13.1 80.7,5.08 ; C9.2 52.73,25.07 ; C9.2 53.29,24.13 ; C9.2 52.17,24.13 ; C9.2 52.73,23.19 ; 43.26,49.78 J14.29 ; J14.29 45.14,49.78 ; J14.29 44.2,48.84 ; J14.29 44.2,50.72 ; J13.2 79.76,3.48 ; J13.2 80.7,2.54 ; J13.2 78.82,2.54 ; J13.2 79.76,1.6 ; J14.51 17.2,49.78 ; J14.51 16.26,50.72 ; J14.51 16.26,48.84 ; J14.51 15.32,49.78 ; J14.11 68,49.78 ; J14.11 66.12,49.78 ; J14.11 67.06,50.72 ; J14.11 67.06,48.84 ; J13.22 54.36,3.48 ; J13.22 53.42,2.54 ; J13.22 54.36,1.6 ; J13.22 55.3,2.54 ; J13.3 77.22,6.02 ; J13.3 77.22,4.14 ; J13.3 78.16,5.08 ; J13.3 76.28,5.08 ; J13.6 74.68,3.48 ; J13.6 75.62,2.54 ; J13.6 74.68,1.6 ; J13.6 73.74,2.54 ; C21.2 84.51,29.49 ; C21.2 83.95,28.55 ; C21.2 83.95,30.43 ; C21.2 83.39,29.49 ; J14.13 65.46,49.78 ; J14.13 64.52,50.72 ; J14.13 63.58,49.78 ; J14.13 64.52,48.84 ; J14.33 39.12,50.72 ; J14.33 40.06,49.78 ; J14.33 38.18,49.78 ; J14.33 39.12,48.84 ; 39.12,1.6 J13.34 ; J13.34 38.18,2.54 ; J13.34 39.12,3.48 ; J13.34 40.06,2.54 ; 20.4,2.54 J13.48 ; J13.48 21.34,3.48 ; J13.48 22.28,2.54 ; J13.48 21.34,1.6 ; 42.84,12.01 C2.2 ; C2.2 43.46,11.52 ; C2.2 43.46,12.51 ; C2.2 44.08,12.01 ; 30.56,49.78 J14.39 ; J14.39 31.5,50.72 ; J14.39 32.44,49.78 ; J14.39 31.5,48.84 ; 76.28,49.78 J14.3 ; J14.3 77.22,48.84 ; J14.3 78.16,49.78 ; J14.3 77.22,50.72 ; J13.16 62.92,2.54 ; J13.16 61.04,2.54 ; J13.16 61.98,3.48 ; J13.16 61.98,1.6 ; 18.8,1.6 J13.50 ; J13.50 17.86,2.54 ; J13.50 18.8,3.48 ; J13.50 19.74,2.54 ; J13.18 59.44,3.48 ; J13.18 58.5,2.54 ; J13.18 59.44,1.6 ; J13.18 60.38,2.54 ; 27.71,25.51 C5.2 ; C5.2 27.71,26.76 ; C5.2 27.22,26.14 ; 13.72,48.84 J14.53 ; J14.53 14.66,49.78 ; J14.53 12.78,49.78 ; J14.53 13.72,50.72 ; 36.58,17.13 C14.2 ; C14.2 35.95,17.63 ; C14.2 37.2,17.63 ; 54.36,48.84 J14.21 ; J14.21 53.42,49.78 ; J14.21 54.36,50.72 ; J14.21 55.3,49.78 ; J13.40 32.44,2.54 ; J13.40 31.5,1.6 ; J13.40 31.5,3.48 ; J13.40 30.56,2.54
  BOTTOM w0.254: C12.2 30.46,17.6 v1(30.29,17.44) ; C17.2 37.57,32.79 37.69,32.66 v1(37.8,32.66) ; C11.2 43.28,26.16 v1(43.79,26.67) ; 28.35,26.14 C5.2 ; C15.2 40.47,21.92 ; C10.2 32.65,35.09 v1(31.79,35.09) ; 71.58,19.96 71.6,19.99
  vias: v1(29.34,31.62) v1(29.33,27.41) v1(29.31,23.37) v1(29.36,29.32) v1(29.36,24.87) v1(30.23,22.02) v1(31.24,27.41) v1(31.21,23.37) v1(31.24,31.62) v1(31.26,29.32) v1(31.26,24.87) v1(33.27,31.62) v1(33.29,29.32) v1(33.27,27.41) v1(33.29,24.87) v1(33.24,23.37) v1(33.27,22.02) v1(35.31,31.62) v1(35.33,29.32) v1(35.3,27.41) v1(35.33,24.87) v1(35.27,23.37) v1(35.28,22.02) v1(36.93,23.37) v1(36.96,31.62) v1(36.98,29.32) v1(36.95,27.41) v1(36.98,24.87) v1(36.96,22.02) v1(39.04,21.95) v1(39.24,27.41) v1(39.21,23.37) v1(39.24,31.62) v1(39.26,29.32) v1(39.26,24.87)
BOARD_5V: length 29.2
  TOP w0.127: J12.1 77.6,25.93 ; J12.1 75.26,28.27 ; J12.1 75.26,23.6 ; J12.1 72.92,25.93
  BOTTOM w0.127: 68.92,19.13 U2.2 67.64,19.61 ; C24.1 68.94,15.8 ; C24.1 68,15.24 ; C24.1 69.88,15.24 ; 67.64,18.34 U2.1 ; U2.1 68.92,17.86 ; U2.1 68.92,18.82
  BOTTOM w0.635: J12.1 77.67,25.93 81.23,29.49 C21.1 81.91,29.11 82.61,28.41 82.61,28.36 83.94,27.04 84.57,27.04 85.27,26.34 C22.1
  vias: v1(68,17.32) v1(67.94,16.59) v1(68.86,17.3) v1(68.86,16.59) v1(69.82,17.3) v1(69.82,16.61)
DDC_CLK: length 37.8
  BOTTOM w0.254: J4.2 26.95,16.48 26.95,18.36 25.98,19.33 25.3,19.33 20.29,24.33 12.34,24.33 11.38,23.37 9.09,23.37 8.66,23.8 8.66,25.27 J3.6
DDC_DATA: length 36.4
  BOTTOM w0.254: J4.3 35.38,10.59 33.68,10.59 27.74,16.54 27.74,18.52 26.26,19.99 25.45,19.99 20.55,24.89 12.09,24.89 11.53,24.33 J3.7
HPD: length 35.8
  TOP w0.254: J3.16 7.72,17.91 v1(10.77,14.86)
  BOTTOM w0.254: v1(10.77,14.86) 14.3,14.86 14.5,14.66 15.65,14.66 16.03,14.27 16.03,12.88 16.54,12.37 24.77,12.37 24.78,12.35 25.08,12.35 25.17,12.37 25.4,12.37 29.62,8.15 31.62,8.15 ; 31.65,8.18 31.62,8.15 ; 31.65,8.18 31.67,8.2 J4.1 ; 31.65,8.18 31.62,8.15 ; 31.62,8.15 30.29,8.15 30.29,8.18 R1.2
OVDD: length 24.8
  TOP w0.127: L3.2 47.37,36.37 ; L3.2 48.06,35.81 ; L3.2 47.37,35.26 ; C13.1 47.93,33.73 ; C13.1 47.37,32.79 ; C13.1 47.37,34.67 ; v1(45.59,33.27) 45.62,33.3
  TOP w0.254: v1(36.8,19.84) 36.79,19.82 U1.18 ; v1(37.11,35.89) 37.3,35.7 37.3,34.9 37.29,34.89 U1.57 ; U1.78 27.62,31.16 27.84,31.38 27.84,32.56 27.71,32.69 v1(27.71,35.48) ; U1.43 43.29,28.66 43.31,28.65 v1(43.41,28.65) ; U1.29 v1(43.23,21.66)
  BOTTOM w0.127: 42,21.92 C15.1 ; C15.1 42.99,21.92 ; C15.1 42.49,21.3 ; C15.1 42.49,22.54 ; 36.16,34.32 C17.1 37.4,34.32 ; C16.1 43.31,29.36 ; C16.1 42.49,29.98 ; C16.1 42,29.36 ; C16.1 42.49,28.74
  BOTTOM w0.254: C18.1 27.71,33.43 v1(27.71,35.48) ; C14.1 36.58,19.34 36.68,19.44 36.68,19.71 v1(36.8,19.84)
  vias: v1(45.62,35.81)
RX0N_TP: length 32.1
  TOP w0.178: U1.91 25.56,24.66 25.47,24.75 22.28,24.75 17.96,29.07 14.64,29.07 14.48,28.91 TP5.1 13.36,28.91 13.2,29.07 11.98,29.07 11.84,28.93 4.52,28.93 4.06,29.39 4.06,34.39 4.65,34.98 5.03,34.98 J3.17
RX0P_TP: length 31.8
  TOP w0.178: U1.90 25.56,25.16 25.47,25.08 22.42,25.08 18.1,29.4 14.64,29.4 14.48,29.57 TP2.1 13.36,29.57 13.2,29.4 11.84,29.4 11.7,29.26 4.66,29.26 4.39,29.52 4.39,32.16 arc(4.43,32.25) 4.52,32.28 arc(4.65,32.41) 4.52,32.54 arc(4.43,32.57) 4.39,32.66 4.39,32.69 arc(4.43,32.78) 4.52,32.82 arc(4.65,32.94) 4.52,33.07 arc(4.43,33.11) 4.39,33.2 4.39,33.32 arc(4.43,33.41) 4.52,33.45 arc(4.65,33.58) 4.52,33.71 arc(4.43,33.74) 4.39,33.83 4.39,34.25 4.78,34.65 5.03,34.65 J3.18
RX1N_TP: length 31.9
  TOP w0.178: J3.9 7.72,34.97 6.77,34.02 6.77,33.11 7.14,32.74 12.81,32.74 12.86,32.79 13.04,32.79 13.2,32.64 TP9.1 14.34,32.64 14.49,32.79 18.85,32.79 19.76,31.88 arc(19.86,31.63) 19.76,31.38 19.43,31.05 arc(19.23,30.56) 19.43,30.08 arc(19.91,29.88) 20.4,30.08 20.73,30.41 arc(21.23,30.41) 21.23,29.91 20.9,29.57 arc(20.7,29.09) 20.9,28.6 arc(21.38,28.4) 21.87,28.6 22.2,28.94 arc(22.7,28.94) 22.7,28.43 22.37,28.1 arc(22.17,27.62) 22.37,27.13 arc(22.86,26.93) 23.34,27.13 23.67,27.46 arc(23.92,27.57) 24.18,27.46 24.2,27.44 24.39,27.25 24.5,27.25 24.59,27.17 25.25,27.17 25.33,27.25 25.47,27.25 25.56,27.16 U1.86
RX1P_TP: length 31.7
  TOP w0.178: J3.10 7.22,33.86 7.1,33.73 7.1,33.25 7.27,33.07 10.13,33.07 arc(10.22,33.11) 10.26,33.2 arc(10.39,33.32) 10.52,33.2 arc(10.64,33.07) 10.77,33.2 arc(10.9,33.32) 11.02,33.2 arc(11.15,33.07) 11.28,33.2 arc(11.4,33.32) 11.53,33.2 arc(11.66,33.07) 11.79,33.2 arc(11.91,33.32) 12.04,33.2 arc(12.08,33.11) 12.17,33.07 12.67,33.07 12.73,33.12 13.04,33.12 13.2,33.27 TP7.1 14.34,33.27 14.49,33.12 14.74,33.12 arc(14.83,33.16) 14.87,33.25 arc(15,33.38) 15.12,33.25 arc(15.25,33.12) 15.38,33.25 arc(15.51,33.38) 15.63,33.25 arc(15.76,33.12) 15.89,33.25 arc(16.01,33.38) 16.14,33.25 arc(16.18,33.16) 16.27,33.12 18.98,33.12 19.99,32.11 arc(20.19,31.63) 19.99,31.14 19.66,30.81 arc(19.56,30.56) 19.66,30.31 arc(19.91,30.21) 20.16,30.31 20.49,30.64 arc(21.46,30.64) 21.46,29.67 21.13,29.34 arc(21.03,29.09) 21.13,28.84 arc(21.38,28.73) 21.64,28.84 21.97,29.17 arc(22.94,29.17) 22.94,28.2 22.61,27.87 arc(22.5,27.62) 22.61,27.37 arc(22.86,27.26) 23.11,27.37 23.44,27.7 arc(23.92,27.9) 24.41,27.7 24.53,27.58 24.64,27.58 24.72,27.5 25.11,27.5 25.19,27.58 25.47,27.58 25.56,27.66 U1.85
RX2N_TP: length 31.6
  TOP w0.178: U1.81 25.56,29.66 25.47,29.75 24.42,29.75 24.08,30.08 arc(23.83,30.19) 23.58,30.08 23.55,30.05 arc(23.06,29.85) 22.58,30.05 arc(22.38,30.54) 22.58,31.02 23.38,31.82 arc(23.38,32.33) 22.88,32.33 22.08,31.52 arc(21.59,31.32) 21.11,31.52 arc(20.9,32.01) 21.11,32.49 21.91,33.3 arc(21.91,33.8) 21.41,33.8 21.37,33.77 arc(20.89,33.56) 20.4,33.77 18.84,35.33 16.71,35.33 arc(16.62,35.29) 16.59,35.2 arc(16.46,35.08) 16.33,35.2 arc(16.3,35.29) 16.21,35.33 16.15,35.33 arc(16.06,35.29) 16.03,35.2 arc(15.9,35.08) 15.77,35.2 arc(15.74,35.29) 15.65,35.33 15.58,35.33 arc(15.49,35.29) 15.45,35.2 arc(15.33,35.08) 15.2,35.2 arc(15.07,35.33) 14.95,35.2 arc(14.82,35.08) 14.69,35.2 arc(14.66,35.29) 14.57,35.33 14.31,35.33 14.13,35.15 TP4.1 13.41,35.33 13.02,35.33 arc(12.93,35.29) 12.89,35.2 arc(12.77,35.08) 12.64,35.2 arc(12.51,35.33) 12.39,35.2 arc(12.26,35.08) 12.13,35.2 arc(12.09,35.29) 12,35.33 11.75,35.33 11.38,35.7 arc(11.29,35.74) 11.2,35.7 arc(11.02,35.7) 11.02,35.88 arc(11.06,35.97) 11.02,36.06 arc(10.93,36.1) 10.84,36.06 arc(10.66,36.06) 10.66,36.24 arc(10.7,36.33) 10.66,36.42 arc(10.57,36.46) 10.48,36.42 arc(10.3,36.42) 10.3,36.6 arc(10.34,36.69) 10.3,36.78 10.12,36.96 9.15,36.96 8.76,36.56 8.76,36.31 9.3,35.76 J3.1
RX2P_TP: length 31.6
  TOP w0.178: U1.80 25.56,30.16 25.47,30.08 24.56,30.08 24.32,30.32 arc(23.83,30.52) 23.35,30.32 23.32,30.28 arc(23.06,30.18) 22.81,30.28 arc(22.71,30.54) 22.81,30.79 23.62,31.59 arc(23.62,32.56) 22.65,32.56 21.84,31.76 arc(21.59,31.65) 21.34,31.76 arc(21.24,32.01) 21.34,32.26 22.14,33.06 arc(22.14,34.03) 21.17,34.03 21.14,34 arc(20.89,33.89) 20.64,34 18.97,35.66 14.31,35.66 14.13,35.84 TP1.1 13.41,35.66 11.89,35.66 10.26,37.29 9.02,37.29 8.43,36.7 8.43,36.17 8.78,35.82 8.78,35.57 8.51,35.3 8.51,34.98 J3.2
RXCN_TP: length 31.8
  TOP w0.178: U1.94 25.56,23.16 25.5,23.22 19.33,23.22 arc(18.85,23.42) 18.65,23.9 18.65,25.96 arc(18.29,26.31) 17.94,25.96 17.94,23.9 arc(17.25,23.22) 16.57,23.9 16.57,25.96 arc(16.21,26.31) 15.85,25.96 15.85,23.9 arc(15.65,23.42) 15.17,23.22 14.73,23.22 14.68,23.16 TP10.1 13.34,23.16 13.2,23.3 12.56,23.3 12.47,23.22 6.6,23.22 J3.24
RXCP_TP: length 31.9
  TOP w0.178: J3.23 6.6,23.55 12.33,23.55 12.42,23.63 13.2,23.63 13.34,23.77 TP8.1 14.5,23.77 14.73,23.55 15.17,23.55 arc(15.42,23.65) 15.52,23.9 15.52,25.96 arc(16.21,26.64) 16.9,25.96 16.9,23.9 arc(17.25,23.55) 17.61,23.9 17.61,25.96 arc(18.29,26.64) 18.98,25.96 18.98,23.9 arc(19.08,23.65) 19.33,23.55 25.44,23.55 25.56,23.66 U1.93
N03879: length 28.5
  TOP w0.127: v1(28.3,20.92) 27.56,21.66 U1.97
  L4 w0.508: v1(28.3,20.92) 28.81,20.92
  L4 w0.635: v1(49.23,19.91) 39.6,19.91 38.57,20.94 28.83,20.94 28.81,20.92
  BOTTOM w0.254: C20.1 28.01,21.21 v1(28.3,20.92)
  BOTTOM w0.635: L4.2 v1(49.23,19.91) 49.23,21.58 49.7,22.05 C19.1
N04328: length 2.6
  BOTTOM w0.635: L2.1 54.04,26.09 54.06,26.11 J9.2
N04342: length 3.2
  TOP w0.635: L3.1 51.23,35.81 J10.2
N04358: length 2.6
  BOTTOM w0.635: L4.1 J11.2
N05960: length 28.6
  TOP w0.254: U1.10 32.79,17.22 28.27,12.7 25.65,12.7 20.95,8 19.03,8 18.9,8.13 13.21,8.13 11.18,6.1 J13.55
N05964: length 26.8
  TOP w0.254: J13.53 13.72,6.55 14.78,7.62 21.46,7.62 25.83,11.99 28.17,11.99 33.29,17.11 U1.11
N05968: length 24.7
  TOP w0.254: U1.12 33.79,16.85 28.32,11.38 26.24,11.38 21.97,7.11 17.14,7.11 16.26,6.22 J13.51
N05972: length 22.8
  TOP w0.254: U1.13 34.29,16.51 28.6,10.82 26.74,10.82 22.65,6.73 20.65,6.73 20.3,6.38 19.08,6.38 18.8,6.1 J13.49
N05976: length 20.4
  TOP w0.254: J13.47 22.1,5.84 22.3,5.84 23.19,6.73 23.72,6.73 27.23,10.24 28.93,10.24 34.8,16.1 34.8,17.42 34.79,17.43 U1.14
N05980: length 18.6
  TOP w0.254: J13.45 28.47,9.68 29.31,9.68 35.29,15.66 U1.15
N05984: length 17.7
  TOP w0.254: J13.43 26.42,6.58 28.75,8.92 29.54,8.92 35.76,15.14 35.76,17.41 35.79,17.43 U1.16
N05988: length 16.4
  TOP w0.254: U1.17 36.29,17.43 36.27,17.41 36.27,14.66 28.96,7.34 J13.41
N05992: length 16
  TOP w0.254: J13.39 31.5,9.32 37.79,15.62 37.79,17.06 37.8,17.06 37.8,17.49 37.79,17.49 U1.20
N05996: length 15.2
  TOP w0.254: U1.21 38.29,17.43 38.3,17.42 38.3,14.22 34.04,9.96 J13.37
N06000: length 14.3
  TOP w0.254: J13.35 36.58,11.33 38.79,13.54 U1.22
N06004: length 13.5
  TOP w0.254: U1.23 39.29,13.1 39.12,12.93 J13.33
N06008: length 14.2
  TOP w0.254: J13.31 41.66,9.45 39.79,11.31 U1.24
N06012: length 15
  TOP w0.254: J13.29 44.2,8.76 40.31,12.65 40.31,17.41 40.29,17.43 U1.25
N06016: length 17.8
  TOP w0.254: J13.27 46.74,6.1 46.79,6.15 46.79,7.54 43.84,10.49 43.84,19.46 43.13,20.16 U1.26
N06020: length 19.5
  TOP w0.254: J13.25 49.28,6.1 44.45,10.92 44.45,19.78 43.56,20.67 43.03,20.67 43.02,20.66 U1.27
N06024: length 22.3
  TOP w0.254: J13.23 45.36,11.53 45.36,20.68 43.89,22.15 43.46,22.15 43.44,22.17 43.02,22.17 43.01,22.16 U1.30
N06028: length 24.1
  TOP w0.254: U1.31 43.02,22.66 43.05,22.63 44.32,22.63 46.05,20.9 46.05,13.39 J13.21
N06032: length 25.9
  TOP w0.254: U1.32 43.02,23.16 43.07,23.11 44.86,23.11 46.86,21.11 46.86,15.11 J13.19
N06036: length 27.8
  TOP w0.254: J13.17 47.78,16.74 47.78,21.31 45.44,23.65 43.03,23.65 43.02,23.66 U1.33
N06040: length 29.6
  TOP w0.254: U1.34 43.02,24.16 43.03,24.16 45.85,24.16 48.59,21.41 48.59,18.47 J13.15
N06044: length 31.6
  TOP w0.254: U1.35 43.02,24.66 43.04,24.64 46.51,24.64 49.4,21.74 49.4,20.42 49.44,20.42 49.73,20.12 49.73,19.86 J13.13
N06048: length 33.4
  TOP w0.254: J13.11 46.97,25.16 U1.36
N06052: length 36.1
  TOP w0.254: J13.9 68.58,5.08 48,25.66 U1.37
N06056: length 18.6
  TOP w0.254: J14.48 21.34,43.43 24.81,39.96 24.81,31.95 25.11,31.65 25.53,31.65 25.54,31.66 U1.77
N06060: length 15.2
  TOP w0.254: J14.46 23.88,42.06 28.27,37.67 28.27,34.91 28.29,34.89 U1.75
N06064: length 14.4
  TOP w0.254: J14.44 26.42,41.63 28.79,39.26 U1.74
N06068: length 13.5
  TOP w0.254: J14.42 28.96,40.79 29.29,40.46 U1.73
N06072: length 14.1
  TOP w0.254: J14.40 31.5,46.23 29.79,44.52 U1.72
N06076: length 14.9
  TOP w0.254: U1.71 30.29,43.5 J14.38
N06080: length 15.8
  TOP w0.254: U1.70 30.79,41.46 J14.36
N06084: length 16.6
  TOP w0.254: J14.34 31.29,39.42 31.29,35.31 31.28,35.3 31.28,34.88 31.29,34.87 U1.69
N06088: length 17.9
  TOP w0.254: U1.66 32.79,39.8 38.05,45.06 39.47,45.06 J14.32
N06092: length 19.6
  TOP w0.254: U1.65 33.29,39.31 38.53,44.55 41.5,44.55 J14.30
N06096: length 21.4
  TOP w0.254: J14.28 43.54,44.04 39.04,44.04 33.79,38.79 U1.64
N06100: length 23.2
  TOP w0.254: J14.26 47.62,45.59 46.55,45.59 44.46,43.51 39.45,43.51 34.29,38.35 U1.63
N06104: length 25
  TOP w0.254: J14.24 49.53,44.96 46.99,44.96 45.06,43.03 39.88,43.03 34.79,37.94 U1.62
N06108: length 26.8
  TOP w0.254: J14.22 51.33,44.22 47.19,44.22 45.49,42.52 40.28,42.52 35.29,37.53 U1.61
N06112: length 28.5
  TOP w0.254: U1.60 35.79,37.06 40.77,42.04 46.08,42.04 47.57,43.54 53.19,43.54 J14.20
N06116: length 30.4
  TOP w0.254: U1.59 36.29,34.89 36.27,34.91 36.27,36.75 40.82,41.3 46.18,41.3 47.57,42.7 54.89,42.7 J14.18
N06120: length 31.7
  TOP w0.254: J14.16 56.69,41.96 47.88,41.96 46.51,40.59 41.12,40.59 37.79,37.26 U1.56
N06124: length 33.5
  TOP w0.254: J14.14 58.47,41.2 48.26,41.2 46.96,39.9 41.33,39.9 38.29,36.87 U1.55
N06128: length 35.1
  TOP w0.254: U1.54 38.79,36.05 41.94,39.19 47.27,39.19 48.49,40.41 60.22,40.41 J14.12
N06132: length 36.8
  TOP w0.254: U1.53 39.29,35.51 42.16,38.38 47.57,38.38 48.89,39.7 62.05,39.7 J14.10
N06136: length 38.6
  TOP w0.254: J14.8 63.86,38.96 49.43,38.96 48.21,37.74 42.44,37.74 39.79,35.09 U1.52
N06140: length 40.5
  TOP w0.254: J14.6 65.68,38.25 51.64,38.25 50.47,37.08 42.48,37.08 40.29,34.89 U1.51
N06144: length 41.5
  TOP w0.254: J14.4 67.49,37.52 61.98,37.52 56.62,32.16 U1.50
N06148: length 44.2
  TOP w0.254: J14.2 69.27,36.75 62.74,36.75 57.65,31.66 U1.49
N13798: length 12.6
  TOP w0.254: v1(19.74,21.74) 21.06,21.74 SW1.16 21.97,21.72 26.75,16.94 27.39,16.94 28.29,17.84 U1.1
  BOTTOM w0.254: R3.2 v1(19.74,21.74)
N13802: length 13.3
  TOP w0.254: U1.2 28.79,17.43 27.66,16.31 26.11,16.31 21.97,20.45 SW1.15 21.06,20.42 v1(19.71,20.42)
  BOTTOM w0.254: R4.2 v1(19.71,20.42)
N13806: length 13.9
  TOP w0.254: v1(19.79,19.2) 21.06,19.2 SW1.14 21.97,19.18 25.35,15.8 27.91,15.8 29.31,17.2 29.31,18.44 U1.3
  BOTTOM w0.254: R5.2 v1(19.79,19.2)
N13810: length 14.5
  TOP w0.254: U1.4 29.79,17.66 29.78,17.65 29.78,17.42 29.77,17.41 29.77,16.81 28.17,15.21 24.66,15.21 21.97,17.91 SW1.13 v1(19.81,17.91)
  BOTTOM w0.254: R6.2 v1(19.81,17.91)
N13814: length 15.5
  TOP w0.254: U1.7 31.29,17.68 31.05,17.43 31.02,17.43 28.24,14.66 23.95,14.66 21.97,16.64 SW1.12 21.06,16.66 v1(19.81,16.66)
  BOTTOM w0.254: R7.2 v1(19.81,16.66)
N13818: length 10.9
  TOP w0.254: 20.19,15.37 20.17,15.34 18.59,15.34 17.2,13.94 17.2,12.42 J6.1 ; 20.19,15.37 SW1.11 ; 20.19,15.37 v1(19.68,15.37)
  BOTTOM w0.254: R8.2 v1(19.68,15.37)
N13822: length 12.9
  TOP w0.254: U1.100 26.59,19.6 v1(25.76,18.77) ; v1(22.15,14.07) 22.12,14.1 v1(19.76,14.1)
  BOTTOM w0.254: v1(22.15,14.07) 22.81,14.73 22.81,18.29 23.29,18.77 v1(25.76,18.77) ; R2.2 v1(19.76,14.1)
N14714: length 20.5
  TOP w0.254: U1.9 32.29,17.43 28.17,13.31 25.25,13.31 21.49,9.55 21.49,9.33 20.54,8.38 19.19,8.38 19.04,8.53 18.8,8.53 J6.2
N14769: length 16
  TOP w0.254: J6.3 21.11,10.01 25.12,14.02 28.27,14.02 31.79,17.54 U1.8
N17734: length 23.4
  TOP w0.254: U1.44 43.08,29.16 43.09,29.15 43.51,29.15 43.52,29.16 44.91,29.16 44.92,29.16 50.42,29.16 v1(50.88,29.62)
  BOTTOM w0.254: J5.14 61.52,34.04 61.49,34.06 57.05,29.62 v1(50.88,29.62)
N17746: length 21.5
  TOP w0.254: U1.48 58.34,31.16 58.67,31.5 J5.12
N17750: length 22.1
  TOP w0.254: J5.10 60.33,28.96 58.62,30.66 U1.47
N17754: length 22.9
  TOP w0.254: J5.8 61.65,26.42 57.9,30.16 44.93,30.16 44.91,30.18 44.49,30.18 44.49,30.17 43.09,30.17 43.08,30.16 U1.46
N17758: length 23.2
  TOP w0.254: J5.6 63.04,23.88 58.76,28.16 43.69,28.16 43.68,28.15 43.63,28.15 43.62,28.14 43.19,28.14 43.17,28.16 U1.42
N17762: length 25.1
  TOP w0.254: J5.4 62.23,21.34 61.09,22.48 61.09,24.33 57.76,27.66 U1.41
N17766: length 26.3
  TOP w0.254: J5.2 62.13,18.8 60.27,20.65 60.27,23.09 56.2,27.16 51.69,27.16 51.68,27.18 43.58,27.18 43.57,27.17 43.09,27.17 43.08,27.16 U1.40
N17770: length 58.4
  TOP w0.254: J5.13 70.55,34.04 70.57,34.06 R9.1 ; v1(28.19,20.24) 27.78,20.66 U1.99
  BOTTOM w0.254: v1(28.19,20.24) 30.07,18.36 58.8,18.36 59.66,19.23 59.66,30.2 62.33,32.87 64.74,32.87 J5.13
N35472: length 2.3
  TOP w0.127: D1.1 71.2,35.08 71.7,34.57 R10.1
N40612: length 4.6
  TOP w0.127: J8.2 15.93,39.88 ; J8.2 14.99,38.94 ; J8.2 14.05,39.88 ; 17.78,39.34 L1.1 ; L1.1 17.09,39.9 ; L1.1 17.78,40.46

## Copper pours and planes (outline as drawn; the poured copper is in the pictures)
+3.3V on BOTTOM: 70.61,28.09 70.64,21.54 67.49,21.51 67.46,28.12
+3.3V on BOTTOM: 16.59,23.24 16.59,13.23 18.14,13.23 18.14,23.24
+3.3V on L4: 0.52,0.55 0.52,51.72 89.6,51.72 89.6,0.55
AVDD on TOP: 19.1,40.79 19.1,36.37 22.1,36.37 22.1,40.79
AVDD on BOTTOM: 23.93,22.18 23.93,36.3 19.1,36.3 19.1,40.92 26.75,40.92 26.75,22.18
GND_POWER on TOP: 28.7,32.08 28.7,20.29 39.78,20.29 39.78,32.08
GND_POWER on BOTTOM: 0.52,0.54 0.52,51.7 89.59,51.7 89.59,0.54 ; 3 cut-outs
GND_POWER on L2: 0.52,0.55 0.52,51.72 89.58,51.72 89.58,0.55
BOARD_5V on TOP: 67.51,20.07 72.59,20.1 72.59,28.37 72.62,28.4 72.64,28.37 78.03,28.37 78.03,23.47 76.66,21.31 73.18,16.15 70.82,16.13 67.51,16.13
BOARD_5V on BOTTOM: 67.44,20.14 67.44,14.68 70.38,14.68 70.38,20.14
OVDD on TOP: 45.09,36.55 45.09,32.66 48.18,32.66 48.18,36.55
OVDD on BOTTOM: 41.45,19.13 41.45,19.18 36.42,19.18 36.42,21.31 41.45,21.31 41.45,33.73 27.46,33.73 27.46,36.58 41.45,36.58 41.45,36.63 44.17,36.63 44.17,36.58 46.15,36.58 46.15,32.67 44.17,32.67 44.17,19.13
N40612 on TOP: 13.31,40.77 13.31,37.92 18.41,37.92 18.41,40.77

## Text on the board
Ref Des/Silkscreen Bottom: FOR EVALUATION ONLY: | NOT FCC APPROVED FOR RESALE | Pb
User.Comments: PROCESS NOTES | 1. CIRCUITRY ON OUTER LAYERS TO BE PLATED WITH : NICKEL GOLD | 2. SOLDERMASK BOTH SIDES PER ARTWORK  :  BLUE LPI | 3. SILKSCREEN BOTH SIDES PER ARTWORK  :  COLOR = WHITE | GENERAL NOTES. UNLESS OTHERWISE SPECIFIED | 1.  ALL FABRICATION ITEMS MUST MEET OR EXCEED BEST | INDUSTRY PRACTICE : IPC-A-600C (Commercial std.) | 2.  LAMINATE MATERIAL  :  FR4 POLYCLAD 370 or EQUIVALENT | 3.  COPPER WEIGHT  : 1oz START INTERNAL, 1/2oz START EXTERNAL | 4.  FINISHED BOARD THICKNESS :  .062  +/- 10% | 5.  MAXIMUM WARP AND TWIST TO BE :  .005 INCH PER INCH | 6.  MINIMUM COPPER WALL THICKNESS OF PLATED-THRU | HOLES TO BE .001 INCH. THERE MUST BE 1MIL OR GREATER PLATING ON | EACH SIDE OF THE BARREL WHEN VIEWED IN THE CROSS SECTION | 7.  MINIMUM ANNULAR RING OF PLATED-THRU HOLES | TO BE .002 INCH | 8.  MINIMUM ALLOWABLE LINE REDUCTION TO BE | 20% OR .002 WHICHEVER IS GREATER | 10. DIFFERENTIAL LINES ON LAYER 1 WILL FOLLOW THE NEXT SPECIFICATIONS | 11. DIELECTRIC CONSTANTS ARE         CORE : 4.1 | PREPREG : 4.1 | IMPEDANCE CONTROLLED 100 OHMS +/- 10% | 0.005"MIN LINE SPACING +/- 0.001 TOLERANCE | 0.007" WIDTH
Ref Des/Silkscreen Top: GND | 56 | 1 | 1-2=PDO# TO PU | 2-3=PDO# TO SCDT | DFO | PD# | ST | PIXS | STAG# | PDO# | OCK_INV | NC | TFP401PZPEVM | HSDC010 Rev A | 3.3V | 1.5A
XSECTION_CHART: *  SURFACE - AIR 0 MIL | L1: TOP CONDUCTOR - COPPER 0.7 MIL | *  DIELECTRIC - FR-4 8 MIL | L2: L2 PLANE - COPPER 1.4 MIL | *  DIELECTRIC - FR-4 41.8 MIL | L3: L4 PLANE - COPPER 1.4 MIL | L4: BOTTOM CONDUCTOR - COPPER 0.7 MIL | DESIGN CROSS SECTION CHART | ___________________________ | TOTAL THICKNESS 62 MIL | 1-4
User.8: FIGURE | SIZE | 10.0 | 34.0 | 38.0 | 76.0 | 120.0 | 140.0 | 250.0 | DRILL CHART: TOP to BOTTOM | ALL UNITS ARE IN MILS | +3.0/-3.0 | TOLERANCE | PLATED | NON-PLATED | QTY | 119 | 1 | 23 | 3 | 141 | 2 | 4
